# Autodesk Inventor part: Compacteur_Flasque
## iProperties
Created: 2008-12
Part Number: Compacteur_Flasque
Document SubType Name: Modeling
Designer: claivier
Author: claivier
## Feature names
1. Extrusion1
2. Congé1 [Fillet]
3. Coque1
4. Extrusion2
5. Révolution1 [Revolution]
6. Miroir1 [Mirror]
7. Extrusion5
8. Miroir3 [Mirror]
9. Congé2 [Fillet]
10. Perçage1 [Hole]
11. Perçage2 [Hole]
12. Perçage3 [Hole]
13. Perçage4 [Hole]
14. Miroir4 [Mirror]
15. Congé4 [Fillet]
